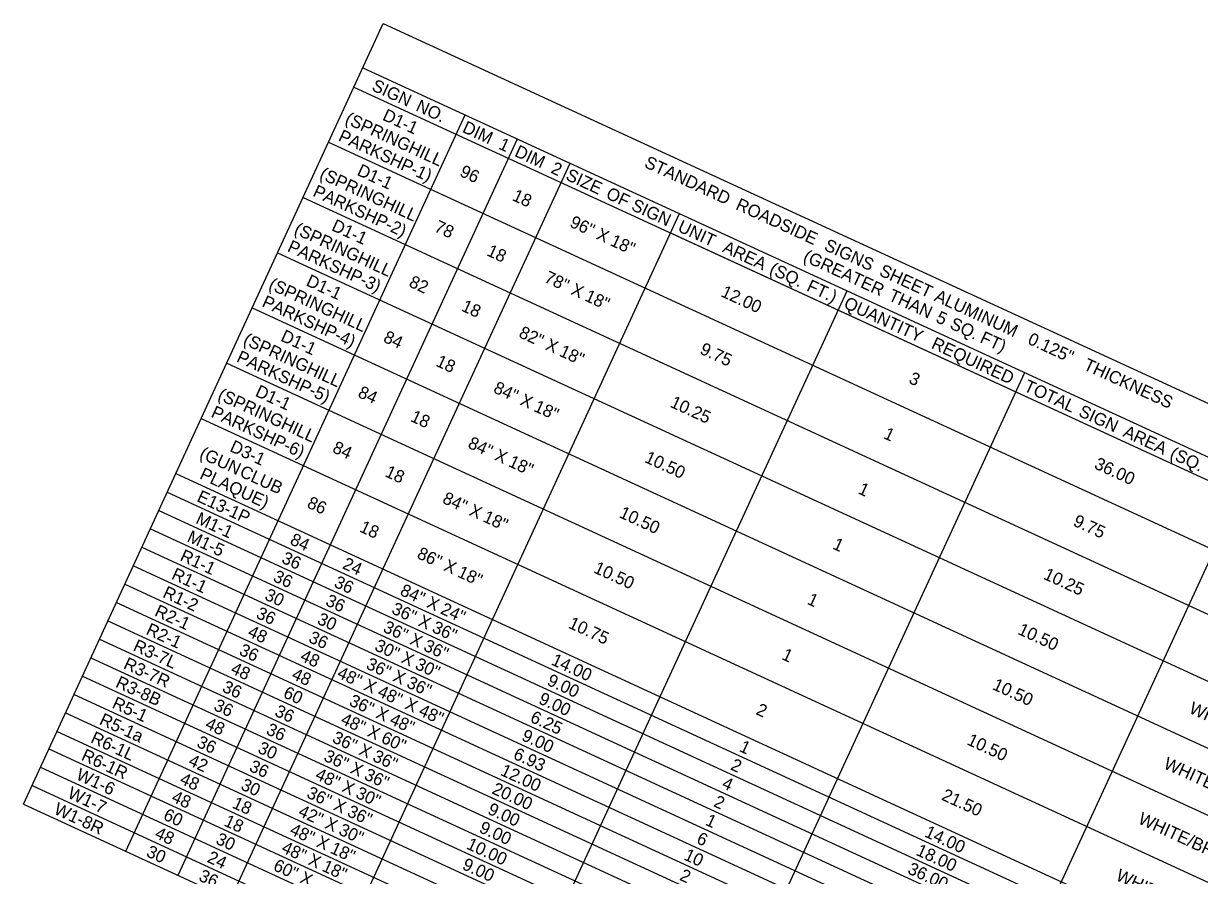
# Model space of a CAD drawing. Extents: x 627405 to 651306, y 367647 to 373430.
# Drawn here: x 650065 to 650630, y 373020 to 373430 of the extents above; entities that cross this region are included whole.
import ezdxf

# ---------------------------------------------------------------- set-up
doc = ezdxf.new("R2010")
doc.units = 0
doc.layers.add('Default', color=7, linetype='Continuous')
doc.layers.add('R_Dimension', color=7, linetype='Continuous')

msp = doc.modelspace()

# ---------------------------------------------------------------- linework, layer by layer
at = {"layer": 'Default'}
for p, q in [((650064.9, 373054.53), (650237.91, 373429.99)), ((650237.91, 373429.99), (650754.16, 373192.09)), ((650228.12, 373408.73), (650744.37, 373170.84)), ((650223.83, 373399.44), (650740.08, 373161.54)), ((650114.04, 373031.88), (650277.26, 373386.09)), ((650139.28, 373020.25), (650302.5, 373374.46)), ((650211.59, 373372.87), (650727.84, 373134.98)), ((650164.52, 373008.63), (650327.74, 373362.83)), ((650199.35, 373346.31), (650715.6, 373108.41)), ((650217.21, 372984.35), (650380.43, 373338.55)), ((650376.14, 373329.25), (650740.08, 373161.54)), ((650187.11, 373319.74), (650703.36, 373081.85)), ((650297.79, 372947.21), (650461.01, 373301.42)), ((650174.87, 373293.17), (650691.12, 373055.28)), ((650162.63, 373266.61), (650678.88, 373028.72)), ((650383.24, 372907.84), (650546.46, 373262.04)), ((650150.38, 373240.04), (650666.63, 373002.15)), ((650138.14, 373213.48), (650654.39, 372975.59)), ((650490.83, 372858.26), (650654.05, 373212.46)), ((650134.06, 373204.62), (650650.31, 372966.73)), ((650129.98, 373195.77), (650646.23, 372957.88)), ((650125.9, 373186.91), (650642.15, 372949.02)), ((650121.82, 373178.06), (650638.07, 372940.17)), ((650117.74, 373169.2), (650633.99, 372931.31)), ((650113.66, 373160.35), (650629.91, 372922.46)), ((650109.58, 373151.49), (650625.83, 372913.6)), ((650105.5, 373142.64), (650621.75, 372904.75)), ((650101.42, 373133.78), (650617.67, 372895.89)), ((650097.34, 373124.93), (650613.59, 372887.04)), ((650093.26, 373116.07), (650609.51, 372878.18)), ((650089.18, 373107.22), (650605.43, 372869.33)), ((650085.1, 373098.36), (650601.35, 372860.47)), ((650081.02, 373089.51), (650597.27, 372851.62)), ((650077.14, 373081.1), (650593.39, 372843.2)), ((650073.06, 373072.24), (650589.31, 372834.35)), ((650068.98, 373063.39), (650585.23, 372825.49)), ((650064.9, 373054.53), (650490.83, 372858.26))]:
    msp.add_line(p, q, dxfattribs=at)
at = {"layer": 'R_Dimension'}
msp.add_line((650237.91, 373429.99), (650237.91, 373429.99), dxfattribs=at)

# ---------------------------------------------------------------- texts
at = {"layer": 'Default'}
for s, p in [('SIGN', (650231.92, 373398.04)), (' NO.', (650251.11, 373389.2)), ('(SPRINGHILL', (650219.07, 373382.22)), ('D1-1', (650237.11, 373383.82)), ('PARK', (650215.86, 373373.79)), ('DIM', (650275.52, 373377.95)), (' 1', (650290.94, 373370.84)), (' SHP-1)', (650233.67, 373365.59)), ('DIM', (650300.63, 373366.38)), ('D1-1', (650224.87, 373357.26)), ('96', (650274.26, 373356.79)), (' 2', (650316.06, 373359.27)), ('STANDARD', (650363.04, 373361.1)), ('(SPRINGHILL', (650206.83, 373355.66)), ('SIZE', (650325.27, 373355.03)), ('PARK', (650203.62, 373347.23)), ('18', (650299.5, 373345.16)), (' OF', (650342.54, 373347.07)), (' SIGN', (650354.72, 373341.45)), (' ROADSIDE', (650404.95, 373341.78)), (' SHP-2)', (650221.43, 373339.02)), ('(SPRINGHILL', (650194.59, 373329.09)), ('D1-1', (650212.63, 373330.69)), ('78', (650262.03, 373330.22)), ('96"', (650327.15, 373332.42)), ('UNIT', (650379.09, 373330.23)), (' X', (650337.92, 373327.46)), (' 18"', (650344.58, 373324.39)), ('PARK', (650191.38, 373320.66)), ('18', (650287.26, 373318.59)), (' AREA', (650398.61, 373321.23)), (' SIGNS', (650447.46, 373322.19)), (' SHP-3)', (650209.19, 373312.46)), ('(GREATER', (650439.44, 373315.98)), ('78"', (650314.91, 373305.85)), (' (SQ.', (650421.14, 373310.85)), (' SHEET', (650473.99, 373309.97)), ('(SPRINGHILL', (650182.35, 373302.53)), ('D1-1', (650200.38, 373304.13)), ('82', (650249.81, 373303.64)), (' X', (650325.68, 373300.89)), (' FT.)', (650439.08, 373302.58)), ('PARK', (650179.14, 373294.1)), (' 18"', (650332.34, 373297.82)), ('12.00', (650399.89, 373298.9)), (' THAN', (650478.4, 373298.02)), (' ALUMINUM', (650500.47, 373297.77)), ('18', (650275.02, 373292.03)), ('QUANTITY', (650458.95, 373293.42)), (' SHP-4)', (650196.94, 373285.89)), (' 5', (650501.28, 373287.48)), (' SQ.', (650507.91, 373284.43)), ('D1-1', (650188.14, 373277.56)), ('84', (650237.5, 373277.11)), ('82"', (650302.67, 373279.29)), (' FT)', (650522.43, 373277.73)), ('(SPRINGHILL', (650170.1, 373275.96)), (' X', (650313.44, 373274.33)), ('9.75', (650389.74, 373271.37)), (' REQUIRED', (650499.06, 373274.94)), (' 0.125"', (650545.38, 373277.07)), ('PARK', (650166.9, 373267.53)), (' 18"', (650320.1, 373271.26)), ('18', (650262.78, 373265.46)), (' THICKNESS', (650572.21, 373264.71)), (' SHP-5)', (650184.7, 373259.33)), ('3', (650490.24, 373257.27)), ('(SPRINGHILL', (650157.86, 373249.4)), ('D1-1', (650175.9, 373251)), ('84', (650225.26, 373250.55)), ('84"', (650290.43, 373252.72)), ('TOTAL', (650545.56, 373253.51)), (' X', (650301.2, 373247.76)), (' 18"', (650307.86, 373244.69)), ('10.25', (650375.45, 373245.75)), ('PARK', (650154.66, 373240.97)), ('18', (650250.54, 373238.9)), (' SIGN', (650569.84, 373242.33)), (' SHP-6)', (650172.46, 373232.76)), ('84"', (650278.18, 373226.16)), ('1', (650478.09, 373230.66)), (' AREA', (650591.21, 373232.48)), ('(GUN', (650149.1, 373221.23)), ('D3-1', (650163.66, 373224.43)), ('84', (650213.02, 373223.98)), (' X', (650288.95, 373221.2)), (' (SQ.', (650613.75, 373222.09)), (' 18"', (650295.61, 373218.13)), ('10.50', (650363.17, 373219.2)), ('36.00', (650579.43, 373216.17)), ('PLAQUE)', (650149.19, 373211.28)), (' CLUB', (650166.34, 373213.29)), ('18', (650238.3, 373212.33)), ('1', (650465.85, 373204.1)), ('E13-1P', (650147.83, 373200.35)), ('84"', (650265.94, 373199.59)), ('86', (650200.81, 373197.4)), (' X', (650276.71, 373194.63)), ('10.50', (650350.93, 373192.64)), ('M1-1', (650147.3, 373189.85)), (' 18"', (650283.37, 373191.56)), ('9.75', (650569.28, 373188.64)), ('M1-5', (650143.12, 373181.05)), ('18', (650226.05, 373185.77)), ('84', (650192.62, 373179.71)), ('1', (650453.6, 373177.53)), ('R1-1', (650139.71, 373171.88)), ('36', (650188.57, 373170.84)), ('86"', (650253.7, 373173.03)), ('24', (650217.85, 373168.08)), (' X', (650264.47, 373168.07)), (' 18"', (650271.13, 373165)), ('10.50', (650338.68, 373166.07)), ('R1-1', (650135.63, 373163.03)), ('36', (650184.48, 373161.98)), ('36', (650213.8, 373159.21)), ('10.25', (650554.99, 373163.02)), ('R1-2', (650131.41, 373154.23)), ('30', (650180.43, 373153.12)), ('84"', (650245.54, 373155.32)), ('36', (650209.72, 373150.35)), (' X', (650256.31, 373150.36)), ('1', (650441.36, 373150.97)), ('R2-1', (650127.47, 373145.32)), ('36', (650176.32, 373144.27)), ('30', (650205.67, 373141.49)), ('36"', (650241.46, 373146.46)), (' 24"', (650262.97, 373147.29)), ('R2-1', (650123.39, 373136.46)), ('36"', (650237.38, 373137.61)), (' X', (650252.23, 373141.5)), (' 36"', (650258.89, 373138.43)), ('10.75', (650326.49, 373139.49)), ('10.50', (650542.7, 373136.47)), ('48', (650172.25, 373135.41)), ('36', (650201.56, 373132.64)), (' X', (650248.15, 373132.65)), ('R3-7L', (650117.15, 373128.6)), ('36', (650168.16, 373126.56)), ('30"', (650233.3, 373128.75)), (' 36"', (650254.81, 373129.58)), ('R3-7R', (650112.54, 373119.99)), ('48', (650197.49, 373123.78)), ('36"', (650229.22, 373119.9)), (' X', (650244.07, 373123.79)), (' 30"', (650250.73, 373120.72)), ('14.00', (650318.28, 373121.8)), ('1', (650429.12, 373124.4)), ('48', (650164.09, 373117.7)), ('48', (650193.41, 373114.93)), ('48"', (650215.25, 373115.6)), (' X', (650239.99, 373114.94)), ('R3-8B', (650108.72, 373111.01)), ('36', (650160, 373108.85)), (' X', (650226.02, 373110.64)), (' 36"', (650246.65, 373111.87)), ('9.00', (650316.25, 373112)), ('10.50', (650530.46, 373109.91)), ('60', (650189.35, 373106.07)), ('36"', (650221.06, 373102.19)), (' 48"', (650232.68, 373107.57)), ('9.00', (650312.17, 373103.15)), ('R5-1', (650107.06, 373101.04)), ('36', (650155.92, 373100)), ('36', (650185.24, 373097.22)), (' X', (650231.83, 373097.23)), (' X', (650245.79, 373101.53)), (' 48"', (650252.45, 373098.46)), ('2', (650416.74, 373097.9)), ('WHITE/BROWN', (650625, 373098.55)), ('R5-1a', (650100.95, 373093.12)), ('48', (650151.85, 373091.14)), ('48"', (650216.98, 373093.33)), (' 48"', (650238.49, 373094.16)), ('6.25', (650308.13, 373094.27)), ('R6-1L', (650096.74, 373084.33)), ('36', (650181.16, 373088.37)), (' X', (650227.75, 373088.37)), ('9.00', (650304, 373085.44)), ('36', (650147.76, 373082.29)), ('30', (650177.1, 373079.5)), ('36"', (650212.9, 373084.48)), (' X', (650223.67, 373079.52)), (' 60"', (650234.41, 373085.3)), ('1', (650408.72, 373080.12)), ('10.50', (650518.22, 373083.34)), ('R6-1R', (650092.24, 373075.94)), ('36"', (650208.82, 373075.62)), (' 36"', (650230.33, 373076.45)), ('6.93', (650299.99, 373076.55)), ('42', (650143.72, 373073.41)), ('36', (650173, 373070.66)), (' X', (650219.59, 373070.66)), ('12.00', (650293.8, 373068.67)), ('2', (650404.5, 373071.33)), ('WHITE/BROWN', (650612.76, 373071.98)), ('W1-6', (650089.71, 373066.63)), ('48', (650139.61, 373064.57)), ('48"', (650204.74, 373066.77)), (' 36"', (650226.25, 373067.59)), ('4', (650400.35, 373062.51)), ('W1-7', (650085.64, 373057.77)), ('30', (650168.94, 373061.79)), ('36"', (650200.65, 373057.91)), (' X', (650215.51, 373061.81)), (' 30"', (650222.17, 373058.74)), ('20.00', (650289.72, 373059.81)), ('21.50', (650505.98, 373056.78)), ('W1-8R', (650079.04, 373050.08)), ('48', (650135.63, 373055.94)), ('18', (650164.85, 373052.94)), (' X', (650211.43, 373052.95)), ('2', (650396.34, 373053.62)), ('60', (650131.67, 373047.3)), ('42"', (650196.57, 373049.06)), (' 36"', (650218.08, 373049.88)), ('9.00', (650287.68, 373050.02)), ('WHITE/BROWN', (650600.52, 373045.42)), ('18', (650160.87, 373044.31)), ('48"', (650192.49, 373040.2)), (' X', (650207.34, 373044.1)), (' 30"', (650214, 373041.03)), ('9.00', (650283.6, 373041.16)), ('1', (650392.4, 373044.7)), ('48', (650127.57, 373038.45)), ('30', (650156.91, 373035.67)), (' X', (650203.26, 373035.24)), ('6', (650388.14, 373035.93)), ('14.00', (650497.82, 373039.07)), ('30', (650123.51, 373029.59)), ('48"', (650188.52, 373031.57)), (' 18"', (650209.92, 373032.17)), ('10.00', (650277.48, 373033.25)), ('18.00', (650493.74, 373030.21)), ('24', (650152.77, 373026.84)), ('60"', (650184.54, 373022.94)), (' X', (650199.29, 373026.61)), ('9.00', (650275.44, 373023.45)), ('10', (650382.04, 373028.01)), ('36', (650148.72, 373017.97)), (' X', (650195.31, 373017.97)), (' 18"', (650205.95, 373023.54)), ('2', (650380.02, 373018.2)), ('36.00', (650489.66, 373021.36)), ('WHITE/GREEN', (650589.81, 373018.15))]:
    msp.add_text(s, height=6, rotation=335.2593, dxfattribs=at).set_placement(p)

doc.saveas('drawing.dxf')
